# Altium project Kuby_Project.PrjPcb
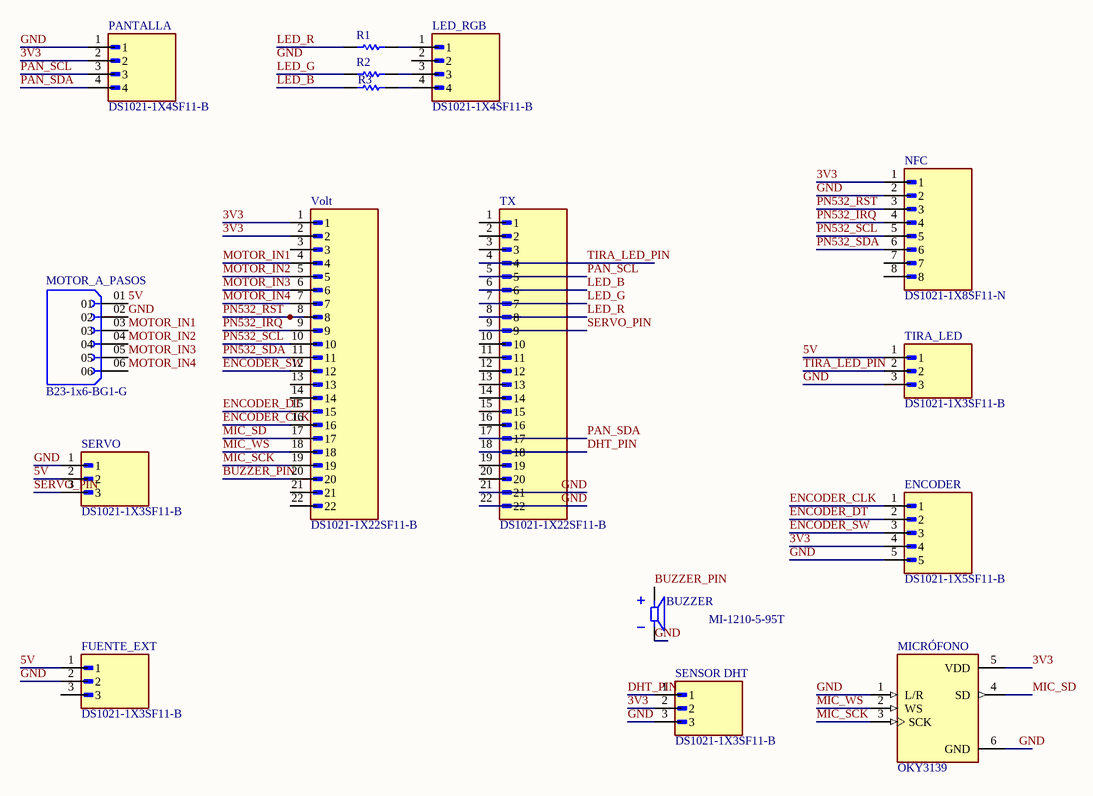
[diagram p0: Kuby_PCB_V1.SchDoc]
1 sheet, 16 parts. Net scope: global (net labels, ports and power ports of the same name join across sheets).
Board file: Kuby_PCB_V1.PcbDoc

## Sheet Kuby_PCB_V1.SchDoc
size A4; SheetNumber: 1; SheetTotal: 1

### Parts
BUZZER  MI-1210-5-95T  [XDCR_CMI-1210-5-95T]
ENCODER  DS1021-1X5SF11-B  [CONNFLY_DS1021-1X5SF11-B]
FUENTE_EXT  DS1021-1X3SF11-B  [CONNFLY_DS1021-1X3SF11-B]
LED_RGB  DS1021-1X4SF11-B  [CONNFLY_DS1021-1X4SF11-B]
MICRÓFONO  OKY3139  [MODULE_OKY3139]
MOTOR_A_PASOS  B23-1x6-BG1-G  [VALCON_B23-1x6-BG1-G]
NFC  DS1021-1X8SF11-N  [CONNFLY_DS1021-1X8SF11-N]
PANTALLA  DS1021-1X4SF11-B  [CONNFLY_DS1021-1X4SF11-B]
R1  (no value)  [RESA60-630X240]
R2  (no value)  [RESA60-630X240]
R3  (no value)  [RESA60-630X240]
SENSOR_DHT  DS1021-1X3SF11-B  [CONNFLY_DS1021-1X3SF11-B]
SERVO  DS1021-1X3SF11-B  [CONNFLY_DS1021-1X3SF11-B]
TIRA_LED  DS1021-1X3SF11-B  [CONNFLY_DS1021-1X3SF11-B]
TX  DS1021-1X22SF11-B  [CONNFLY_DS1021-1X22SF11-B]
Volt  DS1021-1X22SF11-B  [CONNFLY_DS1021-1X22SF11-B]

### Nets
3V3: ENCODER.4 MICRÓFONO.5(VDD) NFC.1 PANTALLA.2 SENSOR_DHT.2 Volt.1 Volt.2
5V: FUENTE_EXT.1 MOTOR_A_PASOS.01 SERVO.2 TIRA_LED.1
BUZZER_PIN: BUZZER.P Volt.20
DHT_PIN: SENSOR_DHT.1 TX.18
ENCODER_CLK: ENCODER.1 Volt.16
ENCODER_DT: ENCODER.2 Volt.15
ENCODER_SW: ENCODER.3 Volt.12
GND: BUZZER.N ENCODER.5 FUENTE_EXT.2 MICRÓFONO.1(L/R) MICRÓFONO.6(GND) MOTOR_A_PASOS.02 NFC.2 PANTALLA.1 SENSOR_DHT.3 SERVO.1 TIRA_LED.3 TX.21 TX.22
LED_B: R3.1 TX.6
LED_G: R2.1 TX.7
LED_R: R1.1 TX.8
MIC_SCK: MICRÓFONO.3(SCK) Volt.19
MIC_SD: MICRÓFONO.4(SD) Volt.17
MIC_WS: MICRÓFONO.2(WS) Volt.18
MOTOR_IN1: MOTOR_A_PASOS.03 Volt.4
MOTOR_IN2: MOTOR_A_PASOS.04 Volt.5
MOTOR_IN3: MOTOR_A_PASOS.05 Volt.6
MOTOR_IN4: MOTOR_A_PASOS.06 Volt.7
PAN_SCL: PANTALLA.3 TX.5
PAN_SDA: PANTALLA.4 TX.17
PN532_IRQ: NFC.4 Volt.9
PN532_RST: NFC.3 Volt.8
PN532_SCL: NFC.5 Volt.10
PN532_SDA: NFC.6 Volt.11
SERVO_PIN: SERVO.3 TX.9
TIRA_LED_PIN: TIRA_LED.2 TX.4
NetLED_RGB_1: LED_RGB.1 R1.2
NetLED_RGB_3: LED_RGB.3 R2.2
NetLED_RGB_4: LED_RGB.4 R3.2

Not connected (* = marked no-connect by the designer): FUENTE_EXT 3; LED_RGB 2; NFC 7 8; TX 1 2 3 10 11 12 13 14 15 16 19 20; Volt 3 13 14 21 22

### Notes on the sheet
- Labels drawn without touching a wire or pin: GND

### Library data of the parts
BUZZER = CMI-1210-5-95T: 12 mm, 5 Vdc, 98 dB, Through Hole, Magnetic Audio Indicator Buzzer; MF: Same Sky
ENCODER = DS1021-1X5SF11-B: 5 position 2.54mm single row vertical pin header through hole; MF: Connfly
FUENTE_EXT SENSOR_DHT SERVO TIRA_LED = DS1021-1X3SF11-B: 3 position 2.54mm single row vertical pin header through hole; MF: Connfly
LED_RGB PANTALLA = DS1021-1X4SF11-B: 4 position 2.54mm single row vertical pin header through hole; MF: Connfly
MICRÓFONO = OKY3139: Module: audio; microphone; I2S; IC: INMP441; SNR: 61dB; 60HzÃ·15kHz; MF: okystar
NFC = DS1021-1X8SF11-N: 8 position 2.54mm single row vertical pin header through hole; MF: Connfly
R1-R3 = CMP-1659-00071-1: Axial Resistor, 100 Ohm, +/- 1%, 0.25 W, -55 to 155 degC, 2-Pin THD, RoHS, Bulk; Voltage Rating: 250 V; Resistance: 4.75 kohm; Power Rating: 250 mW; Type (Resistor): Metal Film
TX Volt = DS1021-1X22SF11-B: 22 position 2.54mm single row vertical pin header through hole; MANUFACTURER: Connfly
